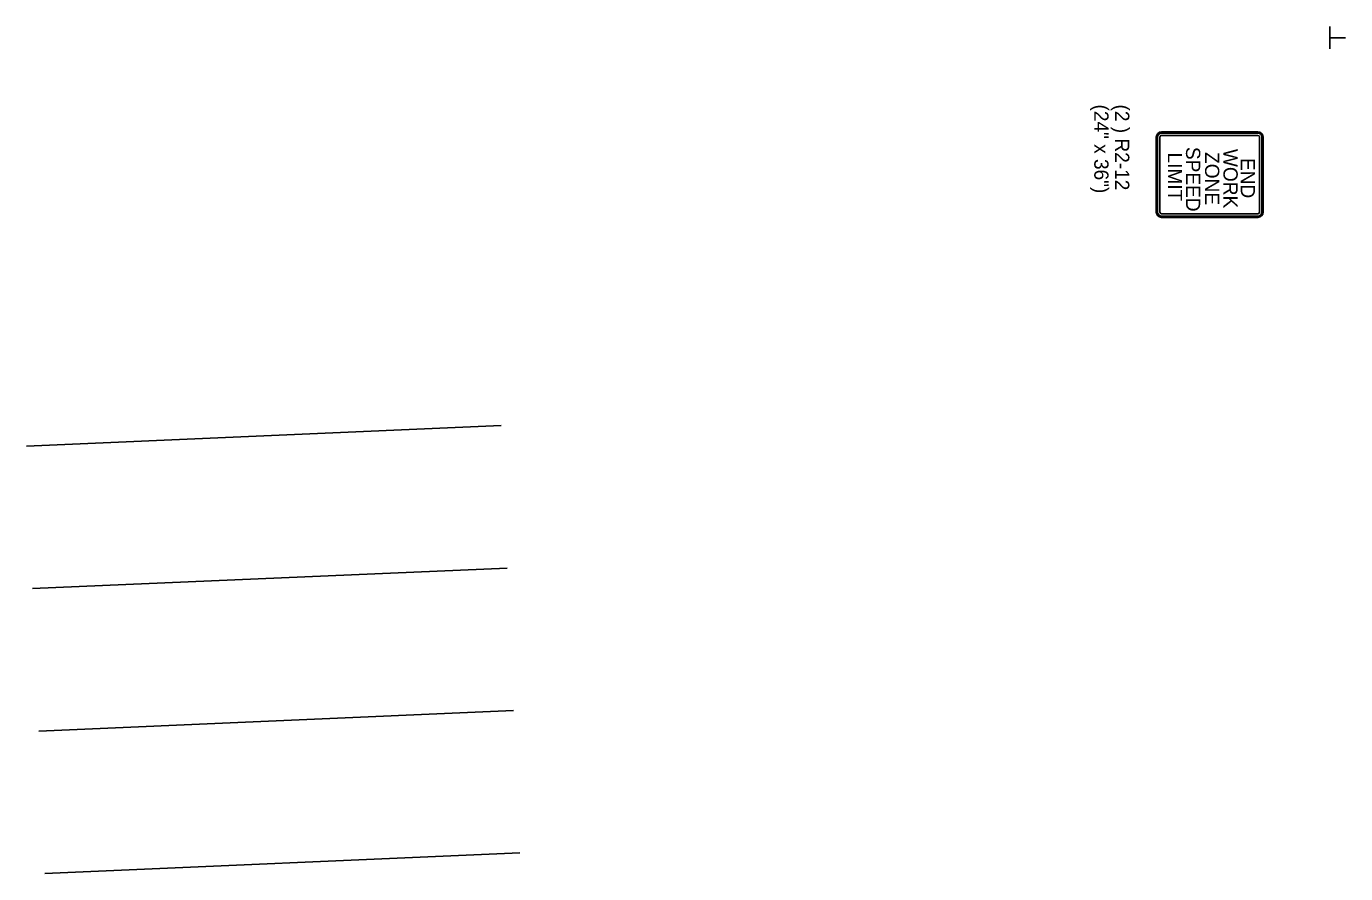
# Model space of a CAD drawing. Extents: x 1930579 to 1934718, y 596452 to 597844.
# Drawn here: x 1930579 to 1931135, y 596452 to 596808 of the extents above; entities that cross this region are included whole.
import ezdxf

# ---------------------------------------------------------------- set-up
doc = ezdxf.new("R2010")
doc.units = 0
for name, color, linetype in [('BR_Pr_Bent_CL', 7, 'Continuous'), ('Default', 7, 'Continuous'), ('P_TC_Signs_Permanent', 7, 'Continuous'), ('R_Annotation', 7, 'Continuous')]:
    doc.layers.add(name, color=color, linetype=linetype)

msp = doc.modelspace()

# ---------------------------------------------------------------- linework, layer by layer
at = {"layer": 'BR_Pr_Bent_CL'}
for p, q in [((1930779.3, 596640.34), (1930579.49, 596631.64)), ((1930781.91, 596580.39), (1930582.1, 596571.7)), ((1930784.52, 596520.45), (1930584.71, 596511.76)), ((1930787.12, 596460.51), (1930587.31, 596451.81))]:
    msp.add_line(p, q, dxfattribs=at)
at = {"layer": 'Default'}
for p, q in [((1931128.11, 596798.78), (1931128.11, 596808.27)), ((1931128.25, 596803.5), (1931134.73, 596803.5))]:
    msp.add_line(p, q, dxfattribs=at)
at = {"layer": 'P_TC_Signs_Permanent'}
for p, q in [((1931097.8, 596763.92), (1931057.3, 596763.92)), ((1931097.8, 596763.35), (1931057.3, 596763.35)), ((1931055.05, 596761.67), (1931055.05, 596730.17)), ((1931055.61, 596761.67), (1931055.61, 596730.17)), ((1931056.55, 596761.67), (1931056.55, 596730.17)), ((1931097.8, 596762.42), (1931057.3, 596762.42)), ((1931098.55, 596730.17), (1931098.55, 596761.67)), ((1931099.48, 596730.17), (1931099.48, 596761.67)), ((1931100.05, 596730.17), (1931100.05, 596761.67)), ((1931057.3, 596729.42), (1931097.8, 596729.42)), ((1931057.3, 596728.48), (1931097.8, 596728.48)), ((1931057.3, 596727.92), (1931097.8, 596727.92))]:
    msp.add_line(p, q, dxfattribs=at)
for centre, radius, start, end in [((1931057.3, 596761.67), 2.25, 90, 180), ((1931057.3, 596761.67), 1.69, 90, 180), ((1931097.8, 596761.67), 2.25, 360, 90), ((1931097.8, 596761.67), 1.69, 360, 90), ((1931057.3, 596761.67), 0.75, 90, 180), ((1931097.8, 596761.67), 0.75, 360, 90), ((1931057.3, 596730.17), 2.25, 180, 270), ((1931057.3, 596730.17), 1.69, 180, 270), ((1931057.3, 596730.17), 0.75, 180, 270), ((1931097.8, 596730.17), 2.25, 270, 360), ((1931097.8, 596730.17), 1.69, 270, 360), ((1931097.8, 596730.17), 0.75, 270, 360)]:
    msp.add_arc(centre, radius, start, end, dxfattribs=at)

# ---------------------------------------------------------------- texts
for s, p in [('LIMIT', (1931059.92, 596755.21)), ('SPEED', (1931067.55, 596757.56)), ('ZONE', (1931075.57, 596755.39)), ('WORK', (1931083.31, 596756.72)), ('END', (1931090.6, 596752.91))]:
    msp.add_text(s, height=6, rotation=270, dxfattribs=at).set_placement(p)
at = {"layer": 'R_Annotation'}
for s, height, p in [('(24" x 36")', 5.9996, (1931028.95, 596775.4)), ('(2 ) R2-12', 6, (1931037.7, 596775.4))]:
    msp.add_text(s, height=height, rotation=270, dxfattribs=at).set_placement(p)

doc.saveas('drawing.dxf')
